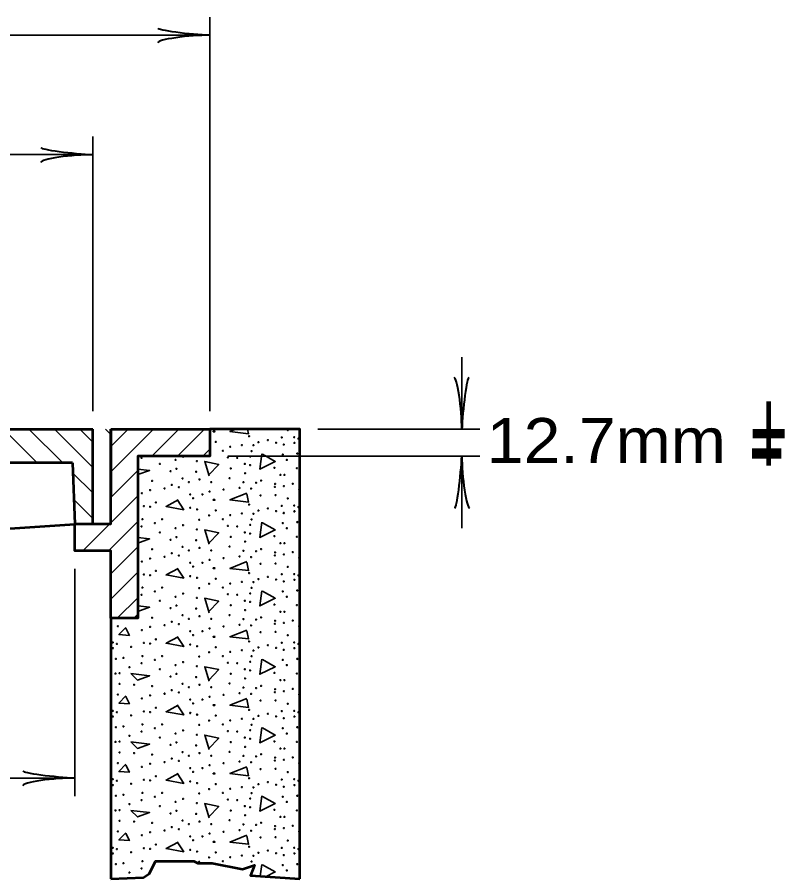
# Model space of a CAD drawing. Extents: x 918 to 1774, y -8 to 536.
# Drawn here: x 1408.1 to 1459.3, y 260.9 to 318.3 of the extents above; entities that cross this region are included whole.
import ezdxf

# ---------------------------------------------------------------- set-up
doc = ezdxf.new("R2010")
doc.units = 0
doc.header["$LTSCALE"] = 1.2
doc.layers.add('1', color=7, linetype='Continuous', lineweight=35)

msp = doc.modelspace()

# ---------------------------------------------------------------- linework, layer by layer
at = {"layer": '1'}
for p, q in [((1420.982, 292.018), (1420.982, 318.275)), ((1344.782, 317.075), (1420.982, 317.075)), ((1413.182, 292.018), (1413.182, 310.322)), ((1352.582, 309.122), (1413.182, 309.122)), ((1437.782, 295.618), (1437.782, 290.818)), ((1407.233, 290.818), (1409.483, 288.568)), ((1408.93, 290.818), (1411.18, 288.568)), ((1410.627, 290.818), (1413.182, 288.263)), ((1412.324, 290.818), (1413.182, 289.96)), ((1414.021, 290.818), (1414.382, 290.457)), ((1414.382, 289.665), (1415.535, 290.818)), ((1414.382, 287.968), (1417.232, 290.818)), ((1417.129, 289.018), (1418.929, 290.818)), ((1418.826, 289.018), (1420.626, 290.818)), ((1428.182, 290.818), (1438.982, 290.818)), ((1420.523, 289.018), (1420.982, 289.477)), ((1422.182, 289.018), (1438.982, 289.018)), ((1437.782, 289.018), (1437.782, 284.218)), ((1411.852, 287.896), (1413.182, 286.566)), ((1414.382, 286.271), (1416.182, 288.071)), ((1411.92, 286.131), (1413.182, 284.868)), ((1414.382, 284.574), (1416.182, 286.374)), ((1412.582, 284.471), (1412.629, 284.518)), ((1412.582, 282.774), (1414.326, 284.518)), ((1414.223, 282.718), (1416.182, 284.677)), ((1414.382, 281.18), (1416.182, 282.98)), ((1411.982, 281.518), (1411.982, 266.367)), ((1414.382, 279.483), (1416.182, 281.283)), ((1414.814, 278.218), (1416.182, 279.586)), ((1353.782, 267.567), (1411.982, 267.567)), ((1424.349, 261.038), (1424.459, 261.812))]:
    msp.add_line(p, q, dxfattribs=at)
at = {"layer": '1', "lineweight": 53}
for p, q in [((1352.582, 290.818), (1413.182, 290.818)), ((1413.182, 284.518), (1413.182, 290.818)), ((1414.382, 290.818), (1414.382, 286.318)), ((1411.827, 288.568), (1411.983, 284.495)), ((1383.989, 282.718), (1411.982, 284.48)), ((1416.182, 278.421), (1415.979, 278.218))]:
    msp.add_line(p, q, dxfattribs=at)
msp.add_lwpolyline([(1414.382, 290.818), (1420.982, 290.818), (1420.982, 289.018), (1416.182, 289.018), (1416.182, 278.218), (1414.382, 278.218), (1414.382, 282.718), (1411.982, 282.718), (1411.982, 284.518), (1414.382, 284.518)], close=True, dxfattribs=at)
for points in [[(1426.982, 260.855), (1426.982, 290.818), (1420.982, 290.818), (1420.982, 289.018), (1416.182, 289.018), (1416.182, 278.218), (1414.382, 278.218), (1414.382, 260.855)], [(1411.827, 288.568), (1384.393, 288.568), (1383.989, 282.718), (1381.775, 282.718), (1381.372, 288.568)], [(1414.382, 260.855), (1416.554, 260.947), (1416.958, 261.217), (1417.363, 262.027), (1419.926, 262.027), (1420.196, 261.892), (1421.14, 261.892), (1423.163, 261.487), (1423.972, 261.757), (1423.702, 261.082), (1426.982, 260.855)]]:
    msp.add_lwpolyline(points, dxfattribs=at)
at = {"layer": '1'}
for points in [[(1422.715, 290.818), (1422.323, 290.66), (1423.571, 290.516), (1423.506, 290.818)], [(1424.507, 289.148), (1425.347, 288.668), (1424.315, 288.163), (1424.459, 289.172)], [(1420.931, 287.708), (1420.643, 288.668), (1421.579, 288.476), (1420.907, 287.756)], [(1416.182, 288.159), (1416.971, 288.067), (1416.182, 287.789)], [(1423.451, 286.555), (1422.323, 286.1), (1423.571, 285.956), (1423.451, 286.507)], [(1418.867, 286.1), (1418.075, 285.668), (1419.251, 285.452), (1418.819, 286.124)], [(1424.507, 284.588), (1425.347, 284.108), (1424.315, 283.603), (1424.459, 284.612)], [(1420.931, 283.148), (1420.643, 284.108), (1421.579, 283.916), (1420.907, 283.196)], [(1416.182, 283.599), (1416.971, 283.507), (1416.182, 283.229)], [(1423.451, 281.995), (1422.323, 281.54), (1423.571, 281.396), (1423.451, 281.947)], [(1418.867, 281.54), (1418.075, 281.108), (1419.251, 280.892), (1418.819, 281.564)], [(1424.507, 280.028), (1425.347, 279.548), (1424.315, 279.043), (1424.459, 280.052)], [(1420.931, 278.588), (1420.643, 279.548), (1421.579, 279.356), (1420.907, 278.636)], [(1416.182, 279.039), (1416.971, 278.947), (1416.182, 278.669)], [(1415.387, 277.603), (1414.931, 277.124), (1415.627, 277.076), (1415.387, 277.555)], [(1423.451, 277.435), (1422.323, 276.98), (1423.571, 276.836), (1423.451, 277.387)], [(1418.867, 276.98), (1418.075, 276.548), (1419.251, 276.332), (1418.819, 277.004)], [(1424.507, 275.468), (1425.347, 274.988), (1424.315, 274.483), (1424.459, 275.492)], [(1420.931, 274.028), (1420.643, 274.988), (1421.579, 274.796), (1420.907, 274.076)], [(1415.387, 273.043), (1414.931, 272.564), (1415.627, 272.516), (1415.387, 272.995)], [(1423.451, 272.875), (1422.323, 272.42), (1423.571, 272.276), (1423.451, 272.827)], [(1418.867, 272.42), (1418.075, 271.988), (1419.251, 271.772), (1418.819, 272.444)], [(1424.507, 270.908), (1425.347, 270.428), (1424.315, 269.923), (1424.459, 270.932)], [(1420.931, 269.468), (1420.643, 270.428), (1421.579, 270.236), (1420.907, 269.516)], [(1415.387, 268.483), (1414.931, 268.004), (1415.627, 267.956), (1415.387, 268.435)], [(1423.451, 268.315), (1422.323, 267.86), (1423.571, 267.716), (1423.451, 268.268)], [(1418.867, 267.86), (1418.075, 267.428), (1419.251, 267.212), (1418.819, 267.884)], [(1420.931, 264.908), (1420.643, 265.868), (1421.579, 265.675), (1420.907, 264.956)], [(1424.507, 266.348), (1425.347, 265.868), (1424.315, 265.363), (1424.459, 266.372)], [(1415.387, 263.923), (1414.931, 263.444), (1415.627, 263.396), (1415.387, 263.875)], [(1423.451, 263.756), (1422.323, 263.3), (1423.571, 263.156), (1423.451, 263.708)], [(1418.867, 263.3), (1418.075, 262.868), (1419.251, 262.651), (1418.819, 263.324)], [(1424.507, 261.788), (1425.347, 261.308), (1424.739, 261.011)]]:
    msp.add_lwpolyline(points, dxfattribs=at)
for points in [[(1415.723, 274.531), (1416.971, 274.387), (1416.155, 274.1)], [(1415.723, 269.971), (1416.971, 269.827), (1416.155, 269.54)], [(1415.723, 265.411), (1416.971, 265.268), (1416.155, 264.98)]]:
    msp.add_lwpolyline(points, close=True, dxfattribs=at)
for centre in [(1421.236, 290.668), (1421.299, 290.668), (1426.182, 290.764), (1421.379, 289.968), (1423.605, 290.35), (1424.225, 289.952), (1424.862, 290.095), (1425.784, 290.27), (1426.611, 290.286), (1426.891, 290.191), (1421.856, 289.379), (1422.349, 289.65), (1423.128, 289.761), (1423.891, 289.745), (1425.402, 289.92), (1425.911, 289.793), (1426.627, 289.904), (1416.433, 288.902), (1419.2, 288.982), (1422.19, 288.934), (1422.81, 288.902), (1423.685, 288.998), (1423.764, 289.364), (1425.848, 289.125), (1426.818, 289.189), (1417.657, 288.504), (1418.707, 288.775), (1420.122, 288.695), (1423.319, 288.504), (1423.669, 288.425), (1425.291, 288.25), (1426.118, 288.775), (1418.373, 288.011), (1418.755, 288.186), (1420.075, 287.979), (1422.381, 288.202), (1423.335, 287.884), (1425.689, 287.773), (1425.959, 287.773), (1426.794, 288.215), (1417.132, 287.375), (1418.452, 287.105), (1419.168, 287.534), (1419.597, 287.295), (1420.297, 287.47), (1421.076, 287.295), (1422.301, 287.55), (1423.224, 287.28), (1424.066, 287.248), (1424.4, 287.391), (1425.339, 287.168), (1426.516, 287.184), (1416.464, 286.554), (1417.005, 286.76), (1417.975, 286.872), (1418.929, 286.951), (1420.965, 286.665), (1421.903, 286.792), (1422.969, 286.904), (1423.732, 286.856), (1425.323, 286.967), (1425.927, 287.031), (1417.387, 285.933), (1419.677, 286.474), (1419.868, 286.219), (1420.488, 286.474), (1421.236, 286.108), (1421.299, 286.108), (1424.369, 286.41), (1425.37, 286.426), (1426.182, 286.204), (1416.592, 285.694), (1417.005, 285.647), (1419.677, 285.583), (1420.138, 285.472), (1421.379, 285.408), (1423.605, 285.79), (1424.225, 285.392), (1424.862, 285.535), (1425.402, 285.36), (1425.784, 285.71), (1426.611, 285.726), (1426.891, 285.631), (1416.496, 284.819), (1417.8, 284.819), (1420.281, 284.788), (1420.933, 285.074), (1421.856, 284.819), (1422.349, 285.09), (1423.128, 285.201), (1423.764, 284.804), (1423.891, 285.185), (1425.911, 285.233), (1426.627, 285.344), (1416.433, 284.342), (1417.323, 284.565), (1418.707, 284.215), (1419.2, 284.422), (1422.19, 284.374), (1422.81, 284.342), (1423.685, 284.438), (1425.848, 284.565), (1426.118, 284.215), (1426.818, 284.629), (1417.657, 283.944), (1418.755, 283.626), (1420.122, 284.135), (1422.381, 283.642), (1423.319, 283.944), (1423.669, 283.865), (1425.291, 283.69), (1426.794, 283.655), (1418.373, 283.451), (1420.075, 283.419), (1423.335, 283.324), (1425.689, 283.213), (1425.959, 283.213), (1417.132, 282.815), (1418.452, 282.545), (1419.168, 282.974), (1419.597, 282.735), (1420.297, 282.91), (1421.076, 282.735), (1422.301, 282.99), (1423.224, 282.72), (1424.066, 282.688), (1424.4, 282.831), (1425.339, 282.608), (1426.516, 282.624), (1416.464, 281.994), (1417.005, 282.2), (1417.975, 282.312), (1418.929, 282.391), (1419.677, 281.914), (1420.488, 281.914), (1420.965, 282.105), (1421.903, 282.232), (1422.969, 282.344), (1423.732, 282.296), (1425.323, 282.407), (1425.927, 282.471), (1417.387, 281.373), (1419.868, 281.659), (1421.236, 281.548), (1421.299, 281.548), (1424.369, 281.85), (1425.37, 281.866), (1426.182, 281.644), (1416.592, 281.134), (1417.005, 281.087), (1419.677, 281.023), (1420.138, 280.912), (1421.379, 280.848), (1423.605, 281.23), (1424.225, 280.832), (1424.862, 280.975), (1425.402, 280.8), (1425.784, 281.15), (1426.611, 281.166), (1426.627, 280.784), (1426.891, 281.071), (1416.496, 280.259), (1417.8, 280.259), (1420.281, 280.228), (1420.933, 280.514), (1421.856, 280.259), (1422.349, 280.53), (1423.128, 280.641), (1423.764, 280.244), (1423.891, 280.625), (1425.911, 280.673), (1416.433, 279.782), (1417.323, 280.005), (1418.707, 279.655), (1419.2, 279.862), (1422.19, 279.814), (1422.81, 279.782), (1423.685, 279.878), (1425.848, 280.005), (1426.118, 279.655), (1426.818, 280.069), (1417.657, 279.384), (1418.755, 279.066), (1420.122, 279.575), (1422.381, 279.082), (1423.319, 279.384), (1423.669, 279.305), (1425.291, 279.13), (1426.794, 279.095), (1418.373, 278.891), (1420.075, 278.859), (1423.335, 278.764), (1425.689, 278.653), (1425.959, 278.653), (1414.42, 278.064), (1417.132, 278.255), (1418.452, 277.985), (1419.168, 278.414), (1419.597, 278.175), (1420.297, 278.35), (1421.076, 278.175), (1422.301, 278.43), (1423.224, 278.16), (1424.066, 278.128), (1424.4, 278.271), (1425.339, 278.048), (1425.927, 277.911), (1426.516, 278.064), (1414.858, 277.688), (1416.464, 277.434), (1417.005, 277.64), (1417.975, 277.752), (1418.929, 277.831), (1419.677, 277.354), (1420.488, 277.354), (1420.965, 277.545), (1421.903, 277.672), (1422.969, 277.784), (1423.732, 277.736), (1425.323, 277.847), (1417.387, 276.813), (1419.868, 277.099), (1421.236, 276.988), (1421.299, 276.988), (1424.369, 277.29), (1425.37, 277.306), (1426.182, 277.084), (1414.515, 276.606), (1414.531, 276.224), (1414.795, 276.511), (1415.733, 276.304), (1416.592, 276.574), (1417.005, 276.527), (1419.677, 276.463), (1420.138, 276.352), (1421.379, 276.288), (1423.605, 276.67), (1424.225, 276.272), (1424.862, 276.415), (1425.402, 276.24), (1425.784, 276.59), (1426.611, 276.606), (1426.627, 276.224), (1426.891, 276.511), (1416.496, 275.699), (1417.8, 275.699), (1420.281, 275.668), (1420.933, 275.954), (1421.856, 275.699), (1422.349, 275.97), (1423.128, 276.081), (1423.764, 275.684), (1423.891, 276.065), (1425.911, 276.113), (1414.722, 275.509), (1415.224, 275.572), (1416.433, 275.222), (1417.323, 275.445), (1418.707, 275.095), (1419.2, 275.302), (1420.122, 275.015), (1422.19, 275.254), (1422.81, 275.222), (1423.685, 275.318), (1425.848, 275.445), (1426.118, 275.095), (1426.818, 275.509), (1414.698, 274.535), (1414.969, 274.554), (1415.621, 274.952), (1417.657, 274.824), (1418.755, 274.506), (1422.381, 274.522), (1423.319, 274.824), (1423.669, 274.745), (1425.291, 274.57), (1426.794, 274.535), (1418.373, 274.331), (1420.075, 274.299), (1422.301, 273.87), (1423.335, 274.204), (1425.689, 274.093), (1425.959, 274.093), (1414.42, 273.504), (1414.969, 273.838), (1415.94, 273.79), (1417.132, 273.695), (1418.452, 273.425), (1419.168, 273.854), (1419.597, 273.615), (1420.297, 273.79), (1421.076, 273.615), (1423.224, 273.6), (1424.066, 273.568), (1424.4, 273.711), (1425.339, 273.488), (1425.927, 273.351), (1426.516, 273.504), (1414.858, 273.128), (1416.464, 272.874), (1417.005, 273.08), (1417.975, 273.192), (1418.929, 273.271), (1419.677, 272.794), (1420.488, 272.794), (1420.965, 272.985), (1421.903, 273.112), (1422.969, 273.224), (1423.732, 273.176), (1424.369, 272.73), (1425.323, 273.287), (1425.37, 272.746), (1417.387, 272.253), (1419.868, 272.539), (1421.236, 272.428), (1421.299, 272.428), (1426.182, 272.524), (1414.515, 272.046), (1414.531, 271.664), (1414.795, 271.951), (1415.733, 271.744), (1416.592, 272.014), (1417.005, 271.967), (1419.677, 271.903), (1420.138, 271.792), (1421.379, 271.728), (1423.605, 272.11), (1424.225, 271.712), (1424.862, 271.855), (1425.402, 271.68), (1425.784, 272.03), (1426.611, 272.046), (1426.627, 271.664), (1426.891, 271.951), (1415.224, 271.012), (1416.496, 271.139), (1417.8, 271.139), (1420.281, 271.108), (1420.933, 271.394), (1421.856, 271.139), (1422.349, 271.41), (1423.128, 271.521), (1423.764, 271.124), (1423.891, 271.505), (1425.911, 271.553), (1414.722, 270.949), (1416.433, 270.662), (1417.323, 270.885), (1418.707, 270.535), (1419.2, 270.742), (1420.122, 270.455), (1422.19, 270.694), (1422.81, 270.662), (1423.685, 270.758), (1425.848, 270.885), (1426.118, 270.535), (1426.818, 270.949), (1414.698, 269.975), (1414.969, 269.994), (1415.621, 270.392), (1417.657, 270.264), (1418.755, 269.946), (1422.381, 269.962), (1423.319, 270.264), (1423.669, 270.185), (1425.291, 270.01), (1426.794, 269.975), (1414.969, 269.278), (1418.373, 269.771), (1419.168, 269.294), (1420.075, 269.739), (1422.301, 269.31), (1423.335, 269.644), (1425.689, 269.533), (1425.959, 269.533), (1414.42, 268.944), (1415.94, 269.23), (1417.132, 269.135), (1418.452, 268.865), (1418.929, 268.711), (1419.597, 269.055), (1420.297, 269.23), (1421.076, 269.055), (1423.224, 269.04), (1424.066, 269.008), (1424.4, 269.151), (1425.323, 268.727), (1425.339, 268.928), (1425.927, 268.791), (1426.516, 268.944), (1414.858, 268.568), (1416.464, 268.314), (1417.005, 268.52), (1417.975, 268.632), (1419.677, 268.234), (1420.488, 268.234), (1420.965, 268.425), (1421.903, 268.552), (1422.969, 268.664), (1423.732, 268.616), (1424.369, 268.17), (1425.37, 268.186), (1417.387, 267.693), (1419.868, 267.979), (1421.236, 267.868), (1421.299, 267.868), (1423.605, 267.55), (1426.182, 267.964), (1414.515, 267.486), (1414.531, 267.104), (1414.795, 267.391), (1415.733, 267.184), (1416.592, 267.454), (1417.005, 267.407), (1419.677, 267.343), (1420.138, 267.232), (1421.379, 267.168), (1424.225, 267.152), (1424.862, 267.295), (1425.402, 267.12), (1425.784, 267.47), (1425.911, 266.993), (1426.611, 267.486), (1426.627, 267.104), (1426.891, 267.391), (1415.224, 266.452), (1416.496, 266.579), (1417.8, 266.579), (1420.281, 266.548), (1420.933, 266.834), (1421.856, 266.579), (1422.349, 266.85), (1423.128, 266.961), (1423.764, 266.564), (1423.891, 266.945), (1414.722, 266.389), (1415.621, 265.832), (1416.433, 266.102), (1417.323, 266.325), (1418.707, 265.975), (1419.2, 266.182), (1420.122, 265.895), (1422.19, 266.134), (1422.81, 266.102), (1423.685, 266.198), (1425.848, 266.325), (1426.118, 265.975), (1426.818, 266.389), (1414.698, 265.415), (1414.969, 265.434), (1417.657, 265.704), (1418.755, 265.386), (1422.381, 265.402), (1423.319, 265.704), (1423.669, 265.625), (1425.291, 265.45), (1426.794, 265.415), (1414.969, 264.718), (1418.373, 265.211), (1419.168, 264.734), (1420.075, 265.179), (1422.301, 264.75), (1423.335, 265.084), (1425.689, 264.973), (1425.959, 264.973), (1414.42, 264.384), (1415.94, 264.67), (1417.132, 264.575), (1418.452, 264.305), (1418.929, 264.151), (1419.597, 264.495), (1420.297, 264.67), (1421.076, 264.495), (1422.969, 264.104), (1423.224, 264.48), (1424.066, 264.448), (1424.4, 264.591), (1425.323, 264.167), (1425.339, 264.368), (1425.927, 264.231), (1426.516, 264.384), (1414.858, 264.008), (1416.464, 263.754), (1417.005, 263.96), (1417.975, 264.072), (1419.677, 263.674), (1420.488, 263.674), (1420.965, 263.865), (1421.903, 263.992), (1423.732, 264.056), (1424.369, 263.61), (1425.37, 263.626), (1417.387, 263.133), (1419.868, 263.419), (1421.236, 263.308), (1421.299, 263.308), (1423.605, 262.99), (1426.182, 263.404), (1414.515, 262.926), (1414.531, 262.544), (1414.795, 262.831), (1415.733, 262.624), (1416.592, 262.894), (1417.005, 262.847), (1419.677, 262.783), (1420.138, 262.672), (1421.379, 262.608), (1423.128, 262.401), (1423.891, 262.385), (1424.225, 262.592), (1424.862, 262.735), (1425.402, 262.56), (1425.784, 262.91), (1425.911, 262.433), (1426.611, 262.926), (1426.627, 262.544), (1426.891, 262.831), (1414.722, 261.829), (1415.224, 261.892), (1416.496, 262.019), (1420.281, 261.988), (1420.933, 262.274), (1421.856, 262.019), (1422.349, 262.29), (1423.764, 262.004), (1426.818, 261.829), (1415.621, 261.272), (1416.433, 261.542), (1425.848, 261.765), (1426.118, 261.415)]:
    msp.add_circle(centre, 0.0318, dxfattribs=at)
for centre, start, end in [((1426.954, 286.808), 27.85843, 332.14157), ((1426.954, 282.248), 27.85843, 332.14157), ((1426.954, 277.688), 27.85843, 332.14157), ((1426.954, 273.128), 27.85843, 332.14157), ((1426.954, 268.568), 27.85843, 332.14157), ((1426.954, 264.008), 27.85843, 332.14157), ((1417.8, 262.019), 13.13607, 166.86393), ((1422.81, 261.542), 17.06003, 140.31684), ((1423.685, 261.638), 62.62244, 154.2517), ((1414.698, 260.855), 27.03956, 157.81244), ((1414.969, 260.874), 13.46436, 171.38764), ((1426.794, 260.855), 19.89382, 152.19147)]:
    msp.add_arc(centre, 0.0318, start, end, dxfattribs=at)
at = {"layer": '1', "lineweight": 40}
for centre, major_axis, ratio, start_param, end_param in [((1419.627, 317.339), (2.108, -0.211), 0.07063, 3.140715, 5.41811), ((1419.662, 316.754), (2.143, 0.187), 0.122415, 0.896353, 3.141593), ((1411.838, 309.375), (2.108, -0.211), 0.07063, 3.140715, 5.41811), ((1411.873, 308.79), (2.143, 0.187), 0.122415, 0.896353, 3.141593), ((1437.451, 292.127), (0.187, -2.143), 0.122415, 0.896353, 3.141593), ((1437.451, 292.127), (0.187, -2.143), 0.122415, 0.896353, 3.141593), ((1438.036, 292.162), (-0.211, -2.108), 0.07063, 3.140715, 5.41811), ((1438.036, 292.162), (-0.211, -2.108), 0.07063, 3.140715, 5.41811), ((1437.528, 287.673), (0.211, 2.108), 0.07063, 3.140715, 5.41811), ((1437.528, 287.673), (0.211, 2.108), 0.07063, 3.140715, 5.41811), ((1438.114, 287.708), (-0.187, 2.143), 0.122415, 0.896353, 3.141593), ((1438.114, 287.708), (-0.187, 2.143), 0.122415, 0.896353, 3.141593), ((1410.627, 267.831), (2.108, -0.211), 0.07063, 3.140715, 5.41811), ((1410.662, 267.245), (2.143, 0.187), 0.122415, 0.896353, 3.141593)]:
    msp.add_ellipse(centre, major_axis=major_axis, ratio=ratio, start_param=start_param, end_param=end_param, dxfattribs=at)

# ---------------------------------------------------------------- texts
at = {"layer": '1', "width": 0.55}
msp.add_text('+', height=6, rotation=180, dxfattribs=at).set_placement((1459.523, 293.431))
at = {"layer": '1', "width": 1.1}
msp.add_text('12.7mm', height=3, dxfattribs=at).set_placement((1439.444, 288.564))
at = {"layer": '1'}
msp.add_text('-', height=6, rotation=180, dxfattribs=at).set_placement((1459.43, 291.512))

doc.saveas('drawing.dxf')
